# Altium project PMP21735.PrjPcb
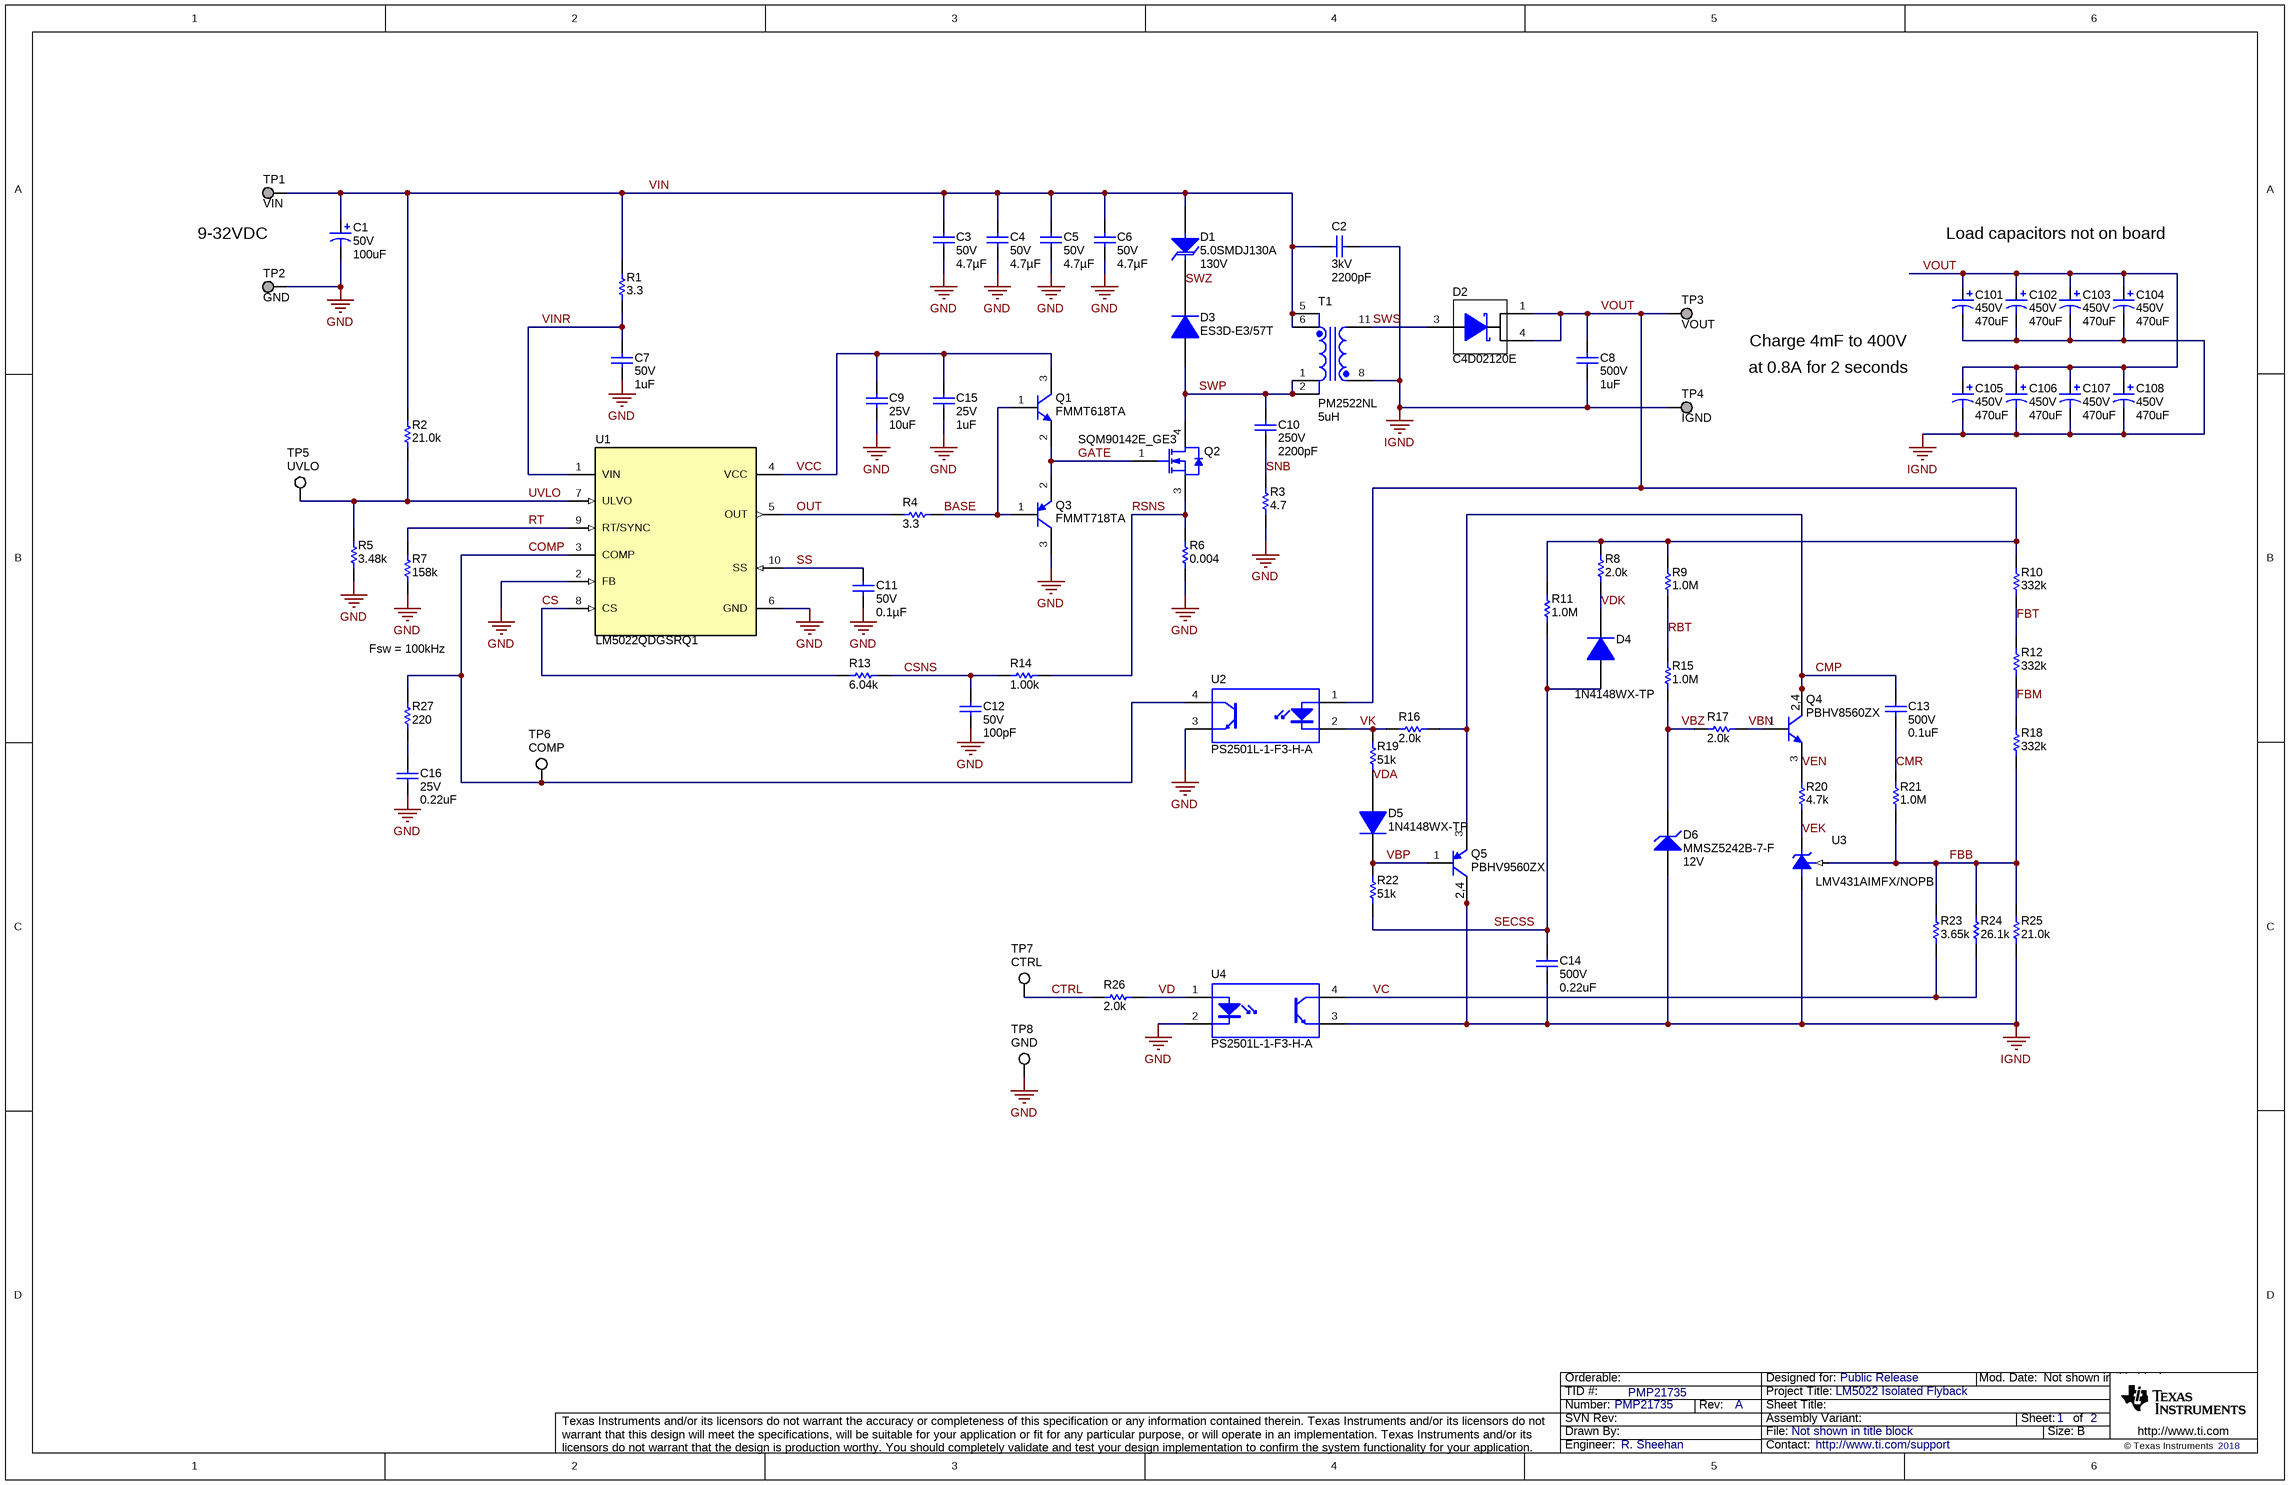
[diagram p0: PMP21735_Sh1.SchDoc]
CopyrightYear: 2018; PCB_Rev: A; PRJ_Customer: Public Release; PRJ_Engineer: R. Sheehan; PRJ_Number: PMP21735; PRJ_Title: LM5022 Isolated Flyback; SCH_Rev: A; TechSupport: http://www.ti.com/support; TID: PMP21735
2 sheets, 83 parts. Net scope: global (net labels, ports and power ports of the same name join across sheets).
Board file: PMP21735_PCB.PcbDoc
Sheets:
  PMP21735_Sh1.SchDoc
  PMP21735_Sh2.SchDoc

## Sheet PMP21735_Sh1.SchDoc
size 431 x 279 mm; Date: Not shown in title block; ApprovedBy: Not shown in title block; CheckedBy: Not shown in title block; Author: Not shown in title block; CompanyName: Not shown in title block; Engineer: Not shown in title block; Organization: Not shown in title block; Address1: Not shown in title block; Address2: Not shown in title block; Address3: Not shown in title block; Address4: Not shown in title block; DocumentNumber: 1; Revision: Use project parameter SCH_Rev; SheetNumber: 1; SheetTotal: 2; PageSetup: Record=PageOptions¦CenterHorizontal=True¦CenterVertical=True¦PrintScale=1.00¦XCorrection=1.00¦YCorrection=1.00¦PrintKind=0¦BorderSize=5000000¦LeftOffset=0¦BottomOffset=0¦Orientation=2¦PaperLength=1000¦PaperWidth=1000¦Scale=100¦PaperSource=15¦PrintQuality=600¦MediaType=1¦DitherType=10¦PaperKind=Letter¦PrintScaleMode=1

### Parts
C1  VDC_V: 50V  ValueDisplayed: 100uF  [SM_RADIAL_F]  (hidden comment: EEE-FK1H101P)
C2  VDC_V: 3kV  ValueDisplayed: 2200pF  [1812_254]  (hidden comment: 1812HC222KAT1A)
C3  VDC_V: 50V  ValueDisplayed: 4.7µF  [1210_280]  (hidden comment: C1210C475K5RACAUTO)
C4  VDC_V: 50V  ValueDisplayed: 4.7µF  [1210_280]  (hidden comment: C1210C475K5RACAUTO)
C5  VDC_V: 50V  ValueDisplayed: 4.7µF  [1210_280]  (hidden comment: C1210C475K5RACAUTO)
C6  VDC_V: 50V  ValueDisplayed: 4.7µF  [1210_280]  (hidden comment: C1210C475K5RACAUTO)
C7  VDC_V: 50V  ValueDisplayed: 1uF  [0805_HV]  (hidden comment: GRM21BR71H105KA12L)
C8  VDC_V: 500V  ValueDisplayed: 1uF  [KPS_600x500x500]  (hidden comment: C2220C105MCR2C7186)
C9  VDC_V: 25V  ValueDisplayed: 10uF  [0805_HV]  (hidden comment: GRM21BZ71E106KE15L)
C10  VDC_V: 250V  ValueDisplayed: 2200pF  [0805_HV]  (hidden comment: GRM21AR72E222KW01D)
C11  VDC_V: 50V  ValueDisplayed: 0.1µF  [0603]  (hidden comment: C0603C104K5RACAUTO)
C12  VDC_V: 50V  ValueDisplayed: 100pF  [0603]  (hidden comment: CGA3E2NP01H101J080AA)
C13  VDC_V: 500V  ValueDisplayed: 0.1uF  [1210_230]  (hidden comment: C1210W104KCRACTU)
C14  VDC_V: 500V  ValueDisplayed: 0.22uF  [2220_220]  (hidden comment: VJ2220Y224KBEAT4X)
C15  VDC_V: 25V  ValueDisplayed: 1uF  [0603]  (hidden comment: GRM188R71E105KA12D)
C16  VDC_V: 25V  ValueDisplayed: 0.22uF  [0603]  (hidden comment: GCM188R71E224KA55D)
C101  VDC_V: 450V  ValueDisplayed: 470uF  [SMQ_3500x4000]  (hidden comment: ESMQ451VSN471MA40S)
C102  VDC_V: 450V  ValueDisplayed: 470uF  [SMQ_3500x4000]  (hidden comment: ESMQ451VSN471MA40S)
C103  VDC_V: 450V  ValueDisplayed: 470uF  [SMQ_3500x4000]  (hidden comment: ESMQ451VSN471MA40S)
C104  VDC_V: 450V  ValueDisplayed: 470uF  [SMQ_3500x4000]  (hidden comment: ESMQ451VSN471MA40S)
C105  VDC_V: 450V  ValueDisplayed: 470uF  [SMQ_3500x4000]  (hidden comment: ESMQ451VSN471MA40S)
C106  VDC_V: 450V  ValueDisplayed: 470uF  [SMQ_3500x4000]  (hidden comment: ESMQ451VSN471MA40S)
C107  VDC_V: 450V  ValueDisplayed: 470uF  [SMQ_3500x4000]  (hidden comment: ESMQ451VSN471MA40S)
C108  VDC_V: 450V  ValueDisplayed: 470uF  [SMQ_3500x4000]  (hidden comment: ESMQ451VSN471MA40S)
D1  5.0SMDJ130A  value 130V  [SMC]
D2  C4D02120E  [DPAK]
D3  ES3D-E3/57T  [SMC]
D4  1N4148WX-TP  [SOD-323]
D5  1N4148WX-TP  [SOD-323]
D6  MMSZ5242B-7-F  value 12V  [SOD-123]
Q1  FMMT618TA  [SOT-23]
Q2  SQM90142E_GE3  [DDPAK]
Q3  FMMT718TA  [SOT-23]
Q4  PBHV8560ZX  [SOT-223]
Q5  PBHV9560ZX  [SOT-223]
R1  ValueDisplayed: 3.3  [1206]  (hidden comment: CRCW12063R30JNEA)
R2  ValueDisplayed: 21.0k  [0603]  (hidden comment: CRCW060321K0FKEA)
R3  ValueDisplayed: 4.7  [2512]  (hidden comment: CRCW25124R70JNEG)
R4  ValueDisplayed: 3.3  [0603]  (hidden comment: CRCW06033R30JNEA)
R5  ValueDisplayed: 3.48k  [0603]  (hidden comment: CRCW06033K48FKEA)
R6  ValueDisplayed: 0.004  [2512]  (hidden comment: CSNL2512FT4L00)
R7  ValueDisplayed: 158k  [0603]  (hidden comment: CRCW0603158KFKEA)
R8  ValueDisplayed: 2.0k  [0805_HV]  (hidden comment: CRCW08052K00JNEA)
R9  ValueDisplayed: 1.0M  [1206]  (hidden comment: CRCW12061M00JNEA)
R10  ValueDisplayed: 332k  [1206]  (hidden comment: CRCW1206332KFKEA)
R11  ValueDisplayed: 1.0M  [0805_HV]  (hidden comment: CRCW08051M00JNEA)
R12  ValueDisplayed: 332k  [1206]  (hidden comment: CRCW1206332KFKEA)
R13  ValueDisplayed: 6.04k  [0603]  (hidden comment: CRCW06036K04FKEA)
R14  ValueDisplayed: 1.00k  [0603]  (hidden comment: CRCW06031K00FKEA)
R15  ValueDisplayed: 1.0M  [1206]  (hidden comment: CRCW12061M00JNEA)
R16  ValueDisplayed: 2.0k  [0805_HV]  (hidden comment: CRCW08052K00JNEA)
R17  ValueDisplayed: 2.0k  [0805_HV]  (hidden comment: CRCW08052K00JNEA)
R18  ValueDisplayed: 332k  [1206]  (hidden comment: CRCW1206332KFKEA)
R19  ValueDisplayed: 51k  [0805_HV]  (hidden comment: CRCW080551K0JNEA)
R20  ValueDisplayed: 4.7k  [0805_HV]  (hidden comment: CRCW08054K70JNEA)
R21  ValueDisplayed: 1.0M  [0805_HV]  (hidden comment: CRCW08051M00JNEA)
R22  ValueDisplayed: 51k  [0805_HV]  (hidden comment: CRCW080551K0JNEA)
R23  ValueDisplayed: 3.65k  [0603]  (hidden comment: RG1608P-3651-B-T5)
R24  ValueDisplayed: 26.1k  [0603]  (hidden comment: CRCW060326K1FKEA)
R25  ValueDisplayed: 21.0k  [0603]  (hidden comment: CRCW060321K0FKEA)
R26  ValueDisplayed: 2.0k  [0603]  (hidden comment: CRCW06032K00JNEA)
R27  ValueDisplayed: 220  [0603]  (hidden comment: CRCW0603220RJNEA)
T1  PM2522NL  value 5uH  [EFD30]
TP1  VIN  [Keystone_5019]
TP2  GND  [Keystone_5019]
TP3  VOUT  [Keystone_5019]
TP4  IGND  [Keystone_5019]
TP5  UVLO  [Testpoint_Keystone_Miniature]
TP6  COMP  [Testpoint_Keystone_Miniature]
TP7  CTRL  [Testpoint_Keystone_Miniature]
TP8  GND  [Testpoint_Keystone_Miniature]
U1  LM5022QDGSRQ1  [DGS0010A_L]
U2  PS2501L-1-F3-H-A  [PS2501L]
U3  LMV431AIMFX/NOPB  [DBZ0003A_N]
U4  PS2501L-1-F3-H-A  [PS2501L]

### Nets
GND: C1.2(-) C3.2 C4.2 C5.2 C6.2 C7.2 C9.2 C11.2 C12.2 C15.2 C16.2 Q3.3(C) R3.1 R5.1 R6.1 R7.1 TP2.1 TP8.1 U1.2(FB) U1.6(GND) U2.3(E) U4.2(K)
IGND: C2.1 C8.2 C14.2 C101.2(-) C102.2(-) C103.2(-) C104.2(-) C105.2(-) C106.2(-) C107.2(-) C108.2(-) D6.2(A) Q5.2(C) Q5.4(C) R25.1 T1.8 TP4.1 U3.3(A) U4.3(E)
BASE: Q1.1(B) Q3.1(B) R4.2
CMP: C13.1 Q4.2(C) Q4.4(C) Q5.3(E) R16.2
CMR: C13.2 R21.2
COMP: R27.2 TP6.1 U1.3(COMP) U2.4(C)
CS: R13.1 U1.8(CS)
CSNS: C12.1 R13.2 R14.1
CTRL: R26.2 TP7.1
FBB: R18.1 R21.1 R23.2 R24.2 R25.2 U3.1(REF)
FBM: R12.1 R18.2
FBT: R10.1 R12.2
GATE: Q1.2(E) Q2.1(G) Q3.2(E)
OUT: R4.1 U1.5(OUT)
RBT: R9.1 R15.2
RSNS: Q2.3(S) R6.2 R14.2
RT: R7.2 U1.9(RT/SYNC)
SECSS: C14.1 D4.2(A) R11.1 R22.1
SNB: C10.2 R3.2
SS: C11.1 U1.10(SS)
SWP: C10.1 D3.2(A) Q2.4(D) T1.1 T1.2
SWS: D2.3(A) T1.11
SWZ: D1.1(K) D3.1(K)
UVLO: R2.1 R5.2 TP5.1 U1.7(ULVO)
VBN: Q4.1(B) R17.2
VBP: D5.1(K) Q5.1(B) R22.2
VBZ: D6.1(K) R15.1 R17.1
VC: R23.1 R24.1 U4.4(C)
VCC: C9.1 C15.1 Q1.3(C) U1.4(VCC)
VD: R26.1 U4.1(A)
VDA: D5.2(A) R19.1
VDK: D4.1(K) R8.2
VEK: R20.1 U3.2(K)
VEN: Q4.3(E) R20.2
VIN: C1.1(+) C2.2 C3.1 C4.1 C5.1 C6.1 D1.2(A) R1.2 R2.2 T1.5 T1.6 TP1.1
VINR: C7.1 R1.1 U1.1(VIN)
VK: R16.1 R19.2 U2.2(K)
VOUT: C8.1 C101.1(+) C102.1(+) C103.1(+) C104.1(+) C105.1(+) C106.1(+) C107.1(+) C108.1(+) D2.1(NC) D2.4(K) R8.1 R9.2 R10.2 R11.2 TP3.1 U2.1(A)
NetC16_1: C16.1 R27.1

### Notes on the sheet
- 9-32VDC
- Load capacitors not on board
- Charge 4mF to 400V
- at 0.8A for 2 seconds
- Fsw = 100kHz

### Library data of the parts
C1 = CMP-0011177-2: CAP, AL, 100 uF, 50 V, +/- 20%, 0.34 ohm, AEC-Q200 Grade 2, SMD; Manufacturer: Panasonic; TaMin_C: -55°C; ESR_ohm: 3.4d; Polarized: Y; SizeAreaWB_mm2: 123.6; U/M: EA; Value: 100uF; TaMax_C: 105°C; SizeZ_mm: 10.2; SizeX_mm: 10; SizeY_mm: 8.3; Cap_Case: F; SizeArea_mm2: 83; CompType: Capacitor; Cap_F: 100µF; IRMS_A: 3.5dA; AEC Grade: 2; AEC Category: Q200
C2 = CMP-0009296-2: CAP, CERM, 2200 pF, 3000 V, +/- 10%, X7R, 1812; Manufacturer: AVX; TaMin_C: -55°C; Polarized: N; SizeAreaWB_mm2: 23.1; Value1: Unknown; U/M: EA; Value: 2200pF; TaMax_C: 125°C; SizeZ_mm: 2.54; SizeX_mm: 4.5; SizeY_mm: 3.2; Cap_Case: 1812; Value2: 3000V; SizeArea_mm2: 14.4; Cap_F: 2.2nF; AEC Category: Q200
C3-C6 = CMP-0079604-1: CAP, CERM, 4.7 µF, 50 V,+/- 10%, X7R, AEC-Q200 Grade 1, 1210; Manufacturer: Kemet; TaMin_C: -55°C; Polarized: N; SizeAreaWB_mm2: 14.7; U/M: EA; Value: 4.7uF; TaMax_C: 125°C; SizeZ_mm: 2.8; SizeX_mm: 3.2; SizeY_mm: 2.5; Cap_Case: 1210; SizeArea_mm2: 8; AEC Qualified: Y; AEC Grade: 1; AEC Category: Q200
C7 = CMP-0008350-2: CAP, CERM, 1 uF, 50 V, +/- 10%, X7R, 0805; Manufacturer: MuRata; TaMin_C: -55°C; Polarized: N; SizeAreaWB_mm2: 6.75; U/M: EA; Value: 1uF; TaMax_C: 125°C; SizeZ_mm: 1.45; SizeX_mm: 2; SizeY_mm: 1.25; Cap_Case: 0805; SizeArea_mm2: 2.5; Cap_F: 1µF; AEC Category: Q200; Value1: Unknown
C8 = CMP-0009328-2: CAP, CERM, 1 uF, 500 V, +/- 20%, X7R, AEC-Q200 Grade 1, 6x5mm; Manufacturer: Kemet; TaMin_C: -55°C; Polarized: N; SizeAreaWB_mm2: 56; Value1: Unknown; U/M: EA; Value: 1uF; TaMax_C: 125°C; SizeZ_mm: 5; SizeX_mm: 6; Cap_Case: 2220; SizeArea_mm2: 30; CompType: Capacitor; AEC Qualified: Y; Cap_F: 1µF; AEC Grade: 1; AEC Category: Q200
C9 = CMP-0008378-2: CAP, CERM, 10 uF, 25 V, +/- 10%, X7R, 0805; Manufacturer: MuRata; TaMin_C: -55°C; Polarized: N; SizeAreaWB_mm2: 6.75; Value1: Unknown; U/M: EA; Value: 10uF; TaMax_C: 125°C; SizeZ_mm: 1.45; SizeX_mm: 2; SizeY_mm: 1.25; Cap_Case: 0805; SizeArea_mm2: 2.5; Cap_F: 10µF; AEC Category: Q200
C10 = CMP-0008253-2: CAP, CERM, 2200 pF, 250 V, +/- 10%, X7R, 0805; Manufacturer: MuRata; Cap_F: 2.2nF; SizeAreaWB_mm2: 6.75; SizeArea_mm2: 2.5; AEC Category: Q200; Value: 2200pF; TaMax_C: 125°C; SizeZ_mm: 1.45; Polarized: N; TaMin_C: -55°C; SizeY_mm: 1.25; U/M: EA; SizeX_mm: 2; Cap_Case: 0805; Value1: Unknown
C11 = CMP-0079602-1: CAP, CERM, 0.1 µF, 50 V,+/- 10%, X7R, AEC-Q200 Grade 1, 0603; Manufacturer: Kemet; TaMin_C: -55°C; Polarized: N; SizeAreaWB_mm2: 4.68; U/M: EA; Value: 0.1uF; TaMax_C: 125°C; SizeZ_mm: 1; SizeX_mm: 1.6; SizeY_mm: 0.8; SizeArea_mm2: 1.28; AEC Qualified: Y; Cap_F: 100nF; AEC Category: Q200
C12 = CMP-0007075-4: CAP, CERM, 100 pF, 50 V, +/- 5%, C0G/NP0, AEC-Q200 Grade 0, 0603; Manufacturer: TDK; TaMin_C: -55°C; Polarized: N; SizeAreaWB_mm2: 4.68; Value1: Unknown; U/M: EA; Value: 100pF; TaMax_C: 150°C; SizeZ_mm: 1; SizeX_mm: 1.6; SizeY_mm: 0.8; SizeArea_mm2: 1.28; AEC Qualified: Y; AEC Grade: 0; AEC Category: Q200
C13 = CMP-0009094-1: CAP, CERM, 0.1 uF, 500 V, +/- 10%, X7R, 1210; Manufacturer: Kemet; TaMin_C: -55°C; Polarized: N; SizeAreaWB_mm2: 14.7; Value1: Unknown; U/M: EA; Value: 0.1uF; TaMax_C: 125°C; SizeZ_mm: 2.3; SizeX_mm: 3.2; SizeY_mm: 2.5; Cap_Case: 1210; SizeArea_mm2: 8; Cap_F: 100nF; AEC Category: Q200
C14 = CMP-0009579-2: CAP, CERM, 0.22 uF, 500 V, +/- 10%, X7R, 2220; Manufacturer: Vishay-Vitramon; TaMin_C: -55°C; Polarized: N; SizeAreaWB_mm2: 53.9; Value1: Unknown; U/M: EA; Value: 0.22uF; TaMax_C: 125°C; SizeZ_mm: 2.2; SizeX_mm: 5.7; SizeY_mm: 5; Cap_Case: 2220; SizeArea_mm2: 28.5; Cap_F: 220nF; AEC Category: Q200
C15 = CMP-0007405-4: CAP, CERM, 1 uF, 25 V, +/- 10%, X7R, 0603; Manufacturer: MuRata; TaMin_C: -55°C; Polarized: N; SizeAreaWB_mm2: 4.68; Value1: Unknown; U/M: EA; Value: 1uF; TaMax_C: 125°C; SizeZ_mm: 1; SizeX_mm: 1.6; SizeY_mm: 0.8; SizeArea_mm2: 1.28; Cap_F: 1µF; AEC Category: Q200
C16 = CMP-0007140-4: CAP, CERM, 0.22 uF, 25 V, +/- 10%, X7R, AEC-Q200 Grade 1, 0603; Manufacturer: MuRata; TaMin_C: -55°C; Polarized: N; SizeAreaWB_mm2: 4.68; U/M: EA; Value: 0.22uF; TaMax_C: 125°C; SizeZ_mm: 1; SizeX_mm: 1.6; SizeY_mm: 0.8; SizeArea_mm2: 1.28; CompType: Capacitor; AEC Qualified: Y; Cap_F: 220nF; AEC Category: Q200; Value1: Unknown
C101-C108 = CMP-0010056-2: CAP, AL, 470 uF, 450 V, +/- 20%, TH; Manufacturer: Chemi-Con; TaMin_C: -25°C; Polarized: Y; SizeAreaWB_mm2: 1369; Value1: Unknown; U/M: EA; Value: 470uF; TaMax_C: 85°C; SizeZ_mm: 42; SizeX_mm: 35; Cap_Case: 35x40mm; SizeArea_mm2: 1225; CompType: Capacitor; AEC Qualified: N; Cap_F: 470µF; IRMS_A: 2.53A; AEC Category: Q200
D1 = CMP-0005706-2: Diode, TVS, Uni, 130 V, 209 Vc, SMC; Manufacturer: Littelfuse; SizeAreaWB_mm2: 83.2686; Value1: 6.5W; U/M: EA; SizeZ_mm: 2.6; SizeX_mm: 8.13; SizeY_mm: 6.22; SizeArea_mm2: 50.5686; AEC Category: Q101; RJA_CperW: 75
D2 = CMP-0076990-1: Diode, Schottky, 1200 V, 10 A, DPAK; Manufacturer: Cree; SizeAreaWB_mm2: 101.7114; Vr_V: 1.2kV; SizeArea_mm2: 64.8114; TJmax_C: 175°C; AEC Category: Q101; Value: 1200V; SizeZ_mm: 2.29; Green_REACh: Incomplete; Io_A: 14A; Vf_V: 1.8V; SizeY_mm: 6.54; Green_Lifecycle: Not Set; U/M: EA; Value1: 10A; SizeX_mm: 9.91; RJC_CperW: 0.88
D3 = CMP-0029041-1: Diode, Ultrafast, 200 V, 3 A, SMC; Manufacturer: Vishay-Semiconductor; Io_A: 3A; Green_Lifecycle: Not Set; SizeAreaWB_mm2: 83.2686; Vr_V: 200V; Green_REACh: Incomplete; TJmax_C: 150°C; U/M: EA; Value: 200V; SizeZ_mm: 2.6; SizeX_mm: 8.13; SizeY_mm: 6.22; Vf_V: 9dV; Value2: 0.9V; SizeArea_mm2: 50.5686; AEC Category: Q101
D4 D5 = CMP-0082069-1: Diode, Switching, 75 V, 0.15 A, SOD-323; Manufacturer: Micro Commercial Components; Vf_V: 1V; Value: 75V; Value1: 0.15A; Io_A: 150mA; TJmax_C: 150°C; RJC_CperW: 625; SizeAreaWB_mm2: 8.695; SizeArea_mm2: 3.645; SizeX_mm: 2.7; SizeY_mm: 1.35; SizeZ_mm: 1; AEC Category: Q101; AEC Qualified: N
D6 = CMP-0005751-2: Diode, Zener, 12 V, 500 mW, SOD-123; Manufacturer: Diodes Inc.; Power_W: 500mW; SizeAreaWB_mm2: 13.095; Value1: 0.5W; RJA_CperW: 350; U/M: EA; SizeZ_mm: 1.35; SizeX_mm: 3.85; SizeY_mm: 1.7; SizeArea_mm2: 6.545; AEC Category: Q101
Q1 = CMP-0000494-2: Transistor, NPN, 20 V, 2.5 A, AEC-Q101, SOT-23; Manufacturer: Diodes Inc.; TaMax_C: 150°C; Value2: 450; Value1: 2.5 A; Vcesat1_V: 1.3dV; SizeX_mm: 2.5; SizeY_mm: 3; TaMin_C: -55°C; IcRated_A: 2.5A; CompType: BJT; SizeZ_mm: 1.1; AEC Qualified: Y; Value: 20 V; SizeArea_mm2: 7.5; NPN: 1; Vceo_V: 20V; PNP: 0; AEC Category: Q101; SizeAreaWB_mm2: 14; U/M: EA
Q2 = CMP-0001092-3: MOSFET, N-CH, 200 V, 65 A, DDPAK; Alternate Manufacturer: None; Manufacturer: Vishay-Siliconix; SizeZ_mm: 4.445; ChType: N; Value2: 85 nC; VdsMax_V: 200V; SizeX_mm: 15.245; SizeY_mm: 10.16; Vgs_V: 20V; Value: 200V; SizeArea_mm2: 154.8892; AEC Category: Q101; IdsMax_A: 95A; SizeAreaWB_mm2: 209.6992; U/M: EA; QgTyp_nC: 90
Q3 = CMP-0000330-2: Transistor, PNP, 20 V, 1.5 A, SOT-23; Manufacturer: Diodes Inc.; TaMax_C: 150°C; Value2: 6; Value1: 1.5 A; Vcesat1_V: 20V; SizeX_mm: 2.5; SizeY_mm: 3; TaMin_C: -55°C; IcRated_A: 1.5A; CompType: BJT; SizeZ_mm: 1.1; Value: 20 V; SizeArea_mm2: 7.5; NPN: 0; PNP: 1; AEC Category: Q101; SizeAreaWB_mm2: 14; U/M: EA
Q4 = CMP-0000450-2: Transistor, NPN, 600 V, 0.5 A, SOT-223; Manufacturer: Nexperia; TaMax_C: 150°C; Value2: 70; Value1: 0.5 A; Vcesat1_V: 100mV; SizeX_mm: 6.5; SizeY_mm: 7; TaMin_C: -55°C; IcRated_A: 0.5; CompType: BJT; SizeZ_mm: 1.6; Value: 600 V; SizeArea_mm2: 45.5; NPN: 1; Vceo_V: 600V; PNP: 0; AEC Category: Q101; SizeAreaWB_mm2: 76.5; U/M: EA
Q5 = CMP-0000371-2: Transistor, PNP, 600 V, 0.5 A, AEC-Q101, SOT-223; Manufacturer: Nexperia; TaMax_C: 150°C; Value2: 70; Value1: 0.5 A; Vcesat1_V: 250mV; SizeX_mm: 6.5; SizeY_mm: 7; TaMin_C: -55°C; IcRated_A: 0.5; CompType: BJT; SizeZ_mm: 1.6; AEC Qualified: Y; Value: 600 V; SizeArea_mm2: 45.5; NPN: 0; Vceo_V: 600V; PNP: 1; AEC Category: Q101; SizeAreaWB_mm2: 76.5; U/M: EA
R1 = CMP-0018677-3: RES, 3.3, 5%, 0.25 W, AEC-Q200 Grade 0, 1206; Manufacturer: Vishay-Dale; Power_W: 250mW; TempCo: 200 ppm/C; Value_Code: 3R30; Value: 3.3; EIA_Code: E24; SizeX_mm: 3.2; SizeY_mm: 1.6; SizeZ_mm: 1.35; Value2: 0.25W; SizeArea_mm2: 5.12; AEC Qualified: Y; VDC_V: 200V; AEC Category: Q200; AEC Grade: 0
R2 R25 = CMP-0022212-4: RES, 21.0 k, 1%, 0.1 W, AEC-Q200 Grade 0, 0603; Manufacturer: Vishay-Dale; Power_W: 100mW; TempCo: 100 ppm/C; Value_Code: 21k0; Value: 21.0k; EIA_Code: E96; Res_ohm: 21k; SizeX_mm: 1.6; SizeY_mm: 0.8; SizeZ_mm: 1; Value2: 0.1W; SizeArea_mm2: 1.28; AEC Qualified: Y; VDC_V: 75V; AEC Category: Q200; AEC Grade: 0
R3 = CMP-0015974-3: RES, 4.7, 5%, 1 W, AEC-Q200 Grade 0, 2512; Manufacturer: Vishay-Dale; Power_W: 1W; TempCo: 200 ppm/C; Value_Code: 4R70; Value: 4.7; EIA_Code: E24; SizeX_mm: 6.3; SizeY_mm: 3.2; SizeZ_mm: 0.71; SizeArea_mm2: 20.16; AEC Qualified: Y; VDC_V: 500V; AEC Grade: 0; AEC Category: Q200
R4 = CMP-0025805-4: RES, 3.3, 5%, 0.1 W, AEC-Q200 Grade 0, 0603; Manufacturer: Vishay-Dale; Power_W: 100mW; TempCo: 200 ppm/C; Value_Code: 3R30; Value: 3.3; EIA_Code: E24; SizeX_mm: 1.6; SizeY_mm: 0.8; SizeZ_mm: 1; Value2: 0.1W; SizeArea_mm2: 1.28; AEC Qualified: Y; VDC_V: 75V; AEC Category: Q200; AEC Grade: 0
R5 = CMP-0022377-4: RES, 3.48 k, 1%, 0.1 W, AEC-Q200 Grade 0, 0603; Manufacturer: Vishay-Dale; Power_W: 100mW; TempCo: 100 ppm/C; Value_Code: 3k48; Value: 3.48k; EIA_Code: E96; SizeX_mm: 1.6; SizeY_mm: 0.8; SizeZ_mm: 1; Value2: 0.1W; SizeArea_mm2: 1.28; AEC Qualified: Y; VDC_V: 75V; AEC Category: Q200; AEC Grade: 0
R6 = CMP-0015757-2: RES, 0.004, 1%, 2 W, 2512; Manufacturer: Stackpole Electronics Inc; Power_W: 2W; TempCo: 50 ppm/C; Value_Code: 4L000; U/M: EA; Value: 0.004; Res_ohm: 4m; SizeX_mm: 6.3; SizeY_mm: 3.2; SizeZ_mm: 0.71; SizeArea_mm2: 20.16; AEC Category: Q200; VDC_V: 200V
R7 = CMP-0022064-4: RES, 158 k, 1%, 0.1 W, AEC-Q200 Grade 0, 0603; Manufacturer: Vishay-Dale; Power_W: 100mW; TempCo: 100 ppm/C; Value: 158k; EIA_Code: E96; SizeX_mm: 1.6; SizeY_mm: 0.8; SizeZ_mm: 1; Value2: 0.1W; SizeArea_mm2: 1.28; AEC Qualified: Y; VDC_V: 75V; AEC Category: Q200; AEC Grade: 0
R8 R16 R17 = CMP-0020510-3: RES, 2.0 k, 5%, 0.125 W, AEC-Q200 Grade 0, 0805; Manufacturer: Vishay-Dale; Power_W: 125mW; TempCo: 200 ppm/C; Value_Code: 2k00; Value: 2.0k; EIA_Code: E24; Res_ohm: 2k; SizeX_mm: 2; SizeY_mm: 1.25; SizeZ_mm: 1.45; Value2: 0.125W; SizeArea_mm2: 2.5; AEC Qualified: Y; VDC_V: 150V; AEC Category: Q200; AEC Grade: 0
R9 R15 = CMP-0018610-3: RES, 1.0 M, 5%, 0.25 W, AEC-Q200 Grade 0, 1206; Manufacturer: Vishay-Dale; Power_W: 250mW; TempCo: 200 ppm/C; Value_Code: 1M00; Value: 1.0Meg; EIA_Code: E24; Res_ohm: 1M; SizeX_mm: 3.2; SizeY_mm: 1.6; SizeZ_mm: 1.35; Value2: 0.25W; SizeArea_mm2: 5.12; CompType: Resistor; AEC Qualified: Y; VDC_V: 200V; AEC Category: Q200; AEC Grade: 0
R10 R12 = CMP-0016911-3: RES, 332 k, 1%, 0.25 W, AEC-Q200 Grade 0, 1206; Manufacturer: Vishay-Dale; Power_W: 250mW; TempCo: 100 ppm/C; Value: 332k; EIA_Code: E96; SizeX_mm: 3.2; SizeY_mm: 1.6; SizeZ_mm: 1.35; Value2: 0.25W; SizeArea_mm2: 5.12; AEC Qualified: Y; VDC_V: 200V; AEC Category: Q200; AEC Grade: 0
R11 R21 = CMP-0020480-3: RES, 1.0 M, 5%, 0.125 W, AEC-Q200 Grade 0, 0805; Manufacturer: Vishay-Dale; Power_W: 125mW; TempCo: 200 ppm/C; Value_Code: 1M00; Value: 1.0Meg; EIA_Code: E24; Res_ohm: 1M; SizeX_mm: 2; SizeY_mm: 1.25; SizeZ_mm: 1.45; Value2: 0.125W; SizeArea_mm2: 2.5; AEC Qualified: Y; VDC_V: 150V; AEC Category: Q200; AEC Grade: 0
R13 = CMP-0022558-4: RES, 6.04 k, 1%, 0.1 W, AEC-Q200 Grade 0, 0603; Manufacturer: Vishay-Dale; Power_W: 100mW; TempCo: 100 ppm/C; Value_Code: 6k04; Value: 6.04k; EIA_Code: E96; SizeX_mm: 1.6; SizeY_mm: 0.8; SizeZ_mm: 1; Value2: 0.1W; SizeArea_mm2: 1.28; AEC Qualified: Y; VDC_V: 75V; AEC Category: Q200; AEC Grade: 0
R14 = CMP-0022109-5: RES, 1.00 k, 1%, 0.1 W, AEC-Q200 Grade 0, 0603; Manufacturer: Vishay-Dale; Power_W: 100mW; TempCo: 100 ppm/C; Value_Code: 1k00; Value: 1.00k; EIA_Code: E96; Res_ohm: 1k; SizeX_mm: 1.6; SizeY_mm: 0.8; SizeZ_mm: 1; Value2: 0.1W; SizeArea_mm2: 1.28; AEC Qualified: Y; VDC_V: 75V; AEC Category: Q200; AEC Grade: 0
R18 = CMP-0016911-3: RES, 332 k, 1%, 0.25 W, AEC-Q200 Grade 0, 1206; Manufacturer: Vishay-Dale; Power_W: 250mW; TempCo: 100 ppm/C; Value: 332k; EIA_Code: E96; SizeX_mm: 3.2; SizeY_mm: 1.6; SizeZ_mm: 1.35; Value2: 0.25W; SizeArea_mm2: 5.12; CompType: Resistor; AEC Qualified: Y; VDC_V: 200V; AEC Category: Q200; AEC Grade: 0
R19 R22 = CMP-0020566-3: RES, 51 k, 5%, 0.125 W, AEC-Q200 Grade 0, 0805; Manufacturer: Vishay-Dale; Power_W: 125mW; TempCo: 200 ppm/C; Value_Code: 51k0; Value: 51k; EIA_Code: E24; SizeX_mm: 2; SizeY_mm: 1.25; SizeZ_mm: 1.45; Value2: 0.125W; SizeArea_mm2: 2.5; AEC Qualified: Y; VDC_V: 150V; AEC Category: Q200; AEC Grade: 0
R20 = CMP-0020559-3: RES, 4.7 k, 5%, 0.125 W, AEC-Q200 Grade 0, 0805; Manufacturer: Vishay-Dale; Power_W: 125mW; TempCo: 200 ppm/C; Value_Code: 4k70; Value: 4.7k; EIA_Code: E24; SizeX_mm: 2; SizeY_mm: 1.25; SizeZ_mm: 1.45; Value2: 0.125W; SizeArea_mm2: 2.5; AEC Qualified: Y; VDC_V: 150V; AEC Category: Q200; AEC Grade: 0
R23 = CMP-0023530-3: RES, 3.65 k, 0.1%, 0.1 W, 0603; Manufacturer: Susumu Co Ltd; Power_W: 100mW; TempCo: 25 ppm/C; Value_Code: 3k65; Value: 3.65k; EIA_Code: E192; SizeX_mm: 1.6; SizeY_mm: 0.8; SizeZ_mm: 1; Value2: 0.1W; SizeArea_mm2: 1.28; VDC_V: 75V; AEC Category: Q200; U/M: EA
R24 = CMP-0022248-4: RES, 26.1 k, 1%, 0.1 W, AEC-Q200 Grade 0, 0603; Manufacturer: Vishay-Dale; Power_W: 100mW; TempCo: 100 ppm/C; Value_Code: 26k1; Value: 26.1k; EIA_Code: E96; SizeX_mm: 1.6; SizeY_mm: 0.8; SizeZ_mm: 1; Value2: 0.1W; SizeArea_mm2: 1.28; AEC Qualified: Y; VDC_V: 75V; AEC Category: Q200; AEC Grade: 0
R26 = CMP-0025768-4: RES, 2.0 k, 5%, 0.1 W, AEC-Q200 Grade 0, 0603; Manufacturer: Vishay-Dale; Power_W: 100mW; TempCo: 200 ppm/C; Value_Code: 2k00; Value: 2.0k; EIA_Code: E24; Res_ohm: 2k; SizeX_mm: 1.6; SizeY_mm: 0.8; SizeZ_mm: 1; Value2: 0.1W; SizeArea_mm2: 1.28; AEC Qualified: Y; VDC_V: 75V; AEC Category: Q200; AEC Grade: 0
R27 = CMP-0025756-4: RES, 220, 5%, 0.1 W, AEC-Q200 Grade 0, 0603; Manufacturer: Vishay-Dale; Power_W: 100mW; TempCo: 200 ppm/C; Value_Code: 220R; Value: 220; EIA_Code: E24; SizeX_mm: 1.6; SizeY_mm: 0.8; SizeZ_mm: 1; Value2: 0.1W; SizeArea_mm2: 1.28; AEC Qualified: Y; VDC_V: 75V; AEC Category: Q200; AEC Grade: 0
T1 = PM2522NL: Transformer, Flyback, EFD30, Np:Ns = 1:6; Manufacturer: Pulse; U/M: EA; Isat: 43A
TP1-TP4 = CMP-0055162-1: Test Point, Miniature, SMT; Manufacturer: Keystone; PartNumber: 5019; CT: TRUE; Green_REACh: Passed; CNHeader: FALSE; Green_Lifecycle: Active
TP5-TP8 = CMP-0055152-1: Test Point, Miniature, SMT; Manufacturer: Keystone; Green_Lifecycle: Active; Green_REACh: Passed; CNHeader: FALSE; CT: TRUE
U1 = CMP-0076391-1: 2.2MHz 60-V Low Side Controller for Boost, SEPIC and Flyback, DGS0010A (VSSOP-10); Manufacturer: Texas Instruments; Alternate PartNumber: LM5022QDGSTQ1; CompType: IC; SizeAreaWB_mm2: 23.6; SizeArea_mm2: 14.7; SizeX_mm: 4.9; SizeY_mm: 3.0; SizeZ_mm: 1.1; U/M: EA
U2 U4 = CMP-0006191-3: Optocoupler, 5 kV, 80-160% CTR, SMT; Manufacturer: California Eastern Laboratories; CTR (Max): 160%; SizeAreaWB_mm2: 76.56; CTR (Min): 80%; SizeZ_mm: 3.8; SizeX_mm: 9.6; SizeY_mm: 4.6; SizeArea_mm2: 44.16; Voltage_Isolation_Vrms: 5kV
U3 = CMP-0071730-1: Low-Voltage (1.24V) Adjustable Precision Shunt Regulators, 3-pin SOT-23, Pb-Free; Manufacturer: Texas Instruments; PowerWise: N; PackageTopMarking: RLA*XTT; CompType: MiscPower

## Sheet PMP21735_Sh2.SchDoc
size 431 x 279 mm; Date: Not shown in title block; ApprovedBy: Not shown in title block; CheckedBy: Not shown in title block; Author: Not shown in title block; CompanyName: Not shown in title block; Engineer: Not shown in title block; Organization: Not shown in title block; Address1: Not shown in title block; Address2: Not shown in title block; Address3: Not shown in title block; Address4: Not shown in title block; DocumentNumber: 2; Revision: Use project parameter SCH_Rev; SheetNumber: 2; SheetTotal: 2; PageSetup: Record=PageOptions¦CenterHorizontal=True¦CenterVertical=True¦PrintScale=1.00¦XCorrection=1.00¦YCorrection=1.00¦PrintKind=0¦BorderSize=5000000¦LeftOffset=0¦BottomOffset=0¦Orientation=2¦PaperLength=1000¦PaperWidth=1000¦Scale=100¦PaperSource=15¦PrintQuality=600¦MediaType=1¦DitherType=10¦PaperKind=Letter¦PrintScaleMode=1
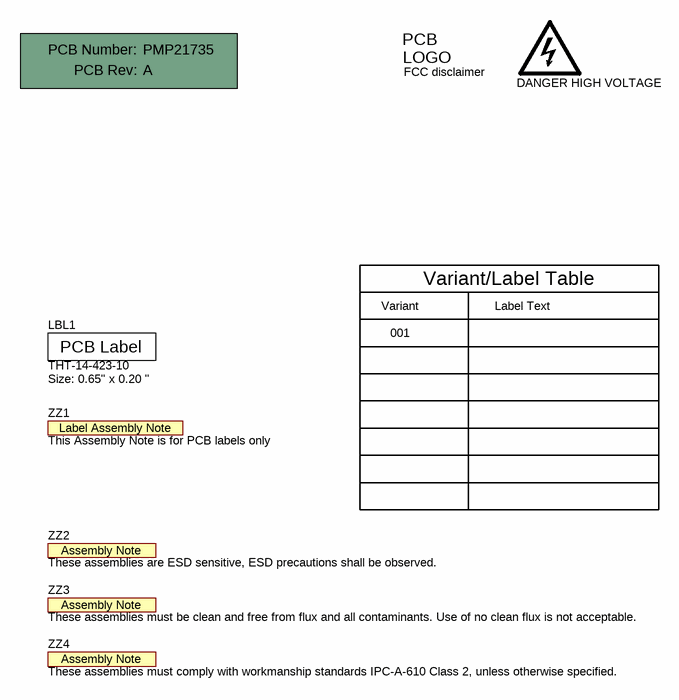
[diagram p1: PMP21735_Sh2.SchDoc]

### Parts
!PCB1  Printed Circuit Board  (value not drawn)  (mechanical)
LBL1  THT-14-423-10  Note: Size: 0.65" x 0.20 "  [Label_650x200]
Logo1  DANGER HIGH VOLTAGE  [IEC_HighVoltage_Small]  (no BOM)
Logo2  FCC disclaimer  [FCC_disclaimer]  (no BOM)
ZZ1  This Assembly Note is for PCB labels only  [AssemblyNoteLabel]  (no BOM)
ZZ2  These assemblies are ESD sensitive, ESD precautions shall be observed.  [AssemblyNote]  (no BOM)
ZZ3  These assemblies must be clean and free from flux and all contaminants. Use of no clean flux is not acceptable.  [AssemblyNote]  (no BOM)
ZZ4  These assemblies must comply with workmanship standards IPC-A-610 Class 2, unless otherwise specified.  [AssemblyNote]  (no BOM)

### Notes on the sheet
- Variant
- Variant/Label Table
- Label Text
- 001

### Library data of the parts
!PCB1 = CMP-0003618-2: Manufacturer: Any; PartNumber: PMP21735
LBL1 = CMP-0003625-1: Thermal Transfer Printable Labels, 0.650" W x 0.200" H - 10,000 per roll; Manufacturer: Brady; CompType: Label
Logo1 = CMP-0074835-1: IEC 61010-1 High Voltage Warning; Lib Reference: IEC_HighVoltage; SymbolCreator: a0412235
Logo2 = CMP-0074847-1: FCC_disclaimer; Library Reference: Logo
ZZ1 = CMP-0003616-3
ZZ2 = CMP-0077236-1
ZZ3 = CMP-0077237-1
ZZ4 = CMP-0077238-1

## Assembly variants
001: not fitted FID1 FID2 FID3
